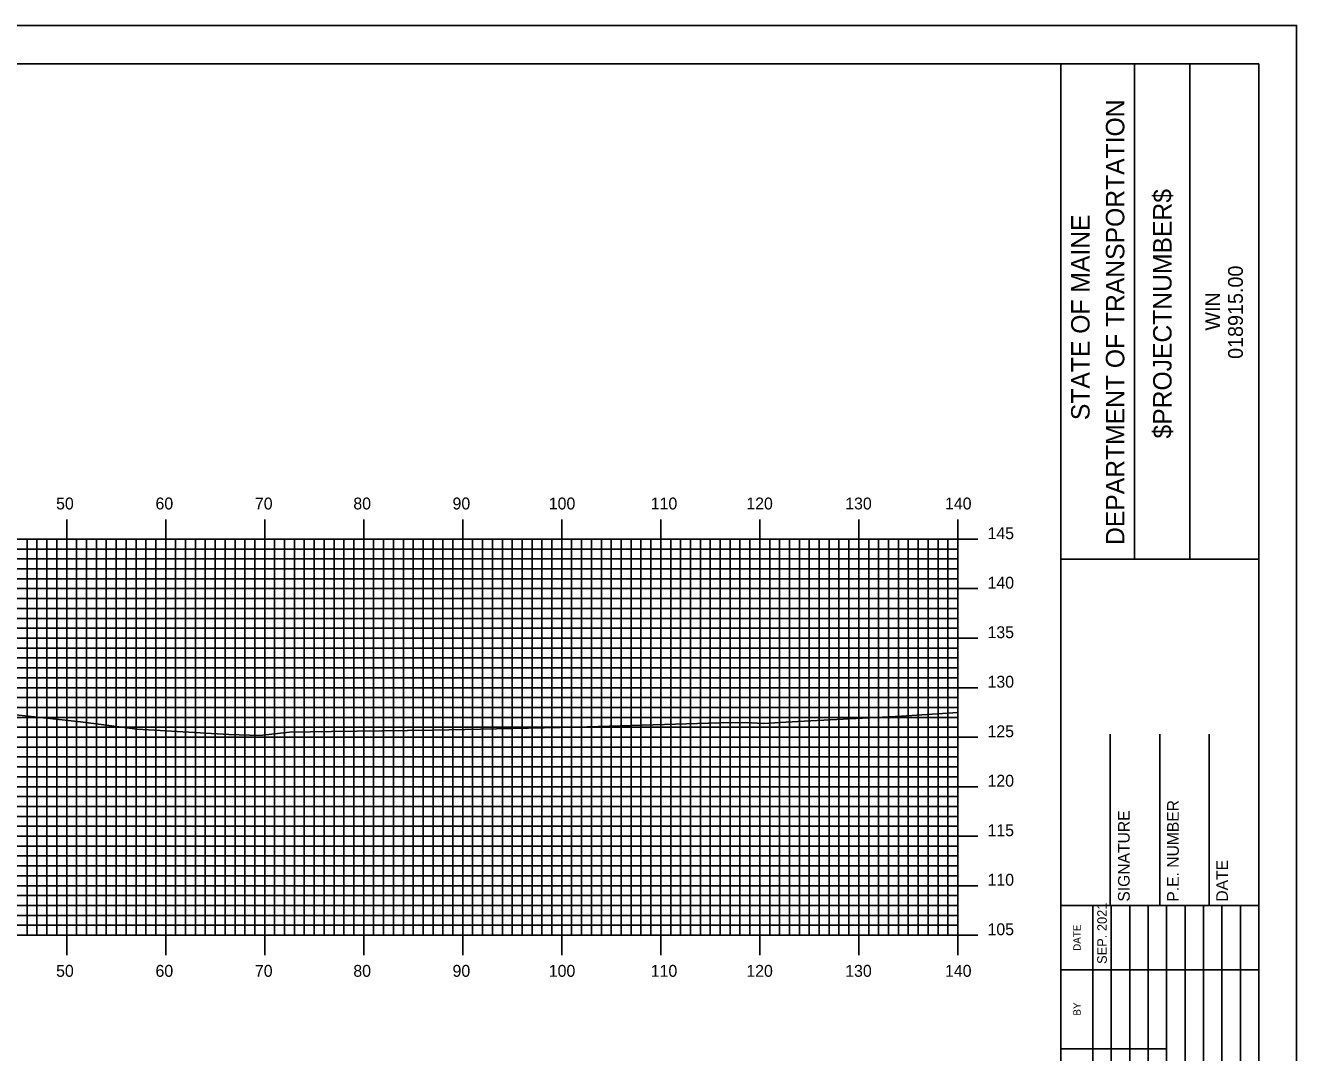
# Model space of a CAD drawing. Extents: x 851753 to 852097, y 364661 to 364881.
# Drawn here: x 851965.1 to 852093.5, y 364777.5 to 364881.3 of the extents above; entities that cross this region are included whole.
import ezdxf

# ---------------------------------------------------------------- set-up
doc = ezdxf.new("R2010")
doc.units = 0
for name, color, linetype in [('BORDER', 7, 'Continuous'), ('H_V ANNOTATION', 7, 'Continuous'), ('MAJOR', 7, 'Continuous'), ('MINOR', 7, 'Continuous'), ('PLOT BOUNDARY', 7, 'Continuous'), ('S_Roadway_Centerline', 7, 'Continuous')]:
    doc.layers.add(name, color=color, linetype=linetype)

msp = doc.modelspace()

# ---------------------------------------------------------------- linework, layer by layer
at = {"layer": 'BORDER'}
for p, q in [((852069.64, 364667.37), (852069.64, 364877.37)), ((852077.1, 364827.36), (852077.1, 364877.36)), ((852082.69, 364827.36), (852082.69, 364877.36)), ((852069.64, 364827.36), (852089.64, 364827.36)), ((852074.64, 364792.38), (852074.64, 364809.67)), ((852079.64, 364792.38), (852079.64, 364809.67)), ((852084.64, 364792.38), (852084.64, 364809.67)), ((852069.64, 364792.38), (852089.64, 364792.38))]:
    msp.add_line(p, q, dxfattribs=at)
msp.add_lwpolyline([(851769.64, 364667.37), (852089.64, 364667.37), (852089.64, 364877.37), (851769.64, 364877.37)], close=True, dxfattribs=at)
for points in [[(852072.87, 364785.88), (852072.87, 364792.38)], [(852074.74, 364757.38), (852074.74, 364792.38)], [(852076.6, 364792.38), (852076.6, 364757.38)], [(852078.46, 364757.38), (852078.46, 364792.38)], [(852080.33, 364757.38), (852080.33, 364792.38)], [(852082.19, 364757.38), (852082.19, 364792.38)], [(852084.05, 364757.38), (852084.05, 364792.38)], [(852085.92, 364757.38), (852085.92, 364792.38)], [(852087.78, 364757.38), (852087.78, 364792.38)], [(852072.87, 364757.38), (852072.87, 364790.96)], [(852069.64, 364785.88), (852089.64, 364785.88)], [(852069.64, 364777.88), (852072.87, 364777.88)], [(852072.87, 364777.88), (852080.33, 364777.88)]]:
    msp.add_lwpolyline(points, dxfattribs=at)
at = {"layer": 'MAJOR'}
for p, q in [((851969.24, 364831.37), (851969.24, 364829.37)), ((851979.24, 364831.37), (851979.24, 364829.37)), ((851989.24, 364831.37), (851989.24, 364829.37)), ((851999.24, 364831.37), (851999.24, 364829.37)), ((852009.24, 364831.37), (852009.24, 364829.37)), ((852019.24, 364831.37), (852019.24, 364829.37)), ((852029.24, 364831.37), (852029.24, 364829.37)), ((852039.24, 364831.37), (852039.24, 364829.37)), ((852049.24, 364831.37), (852049.24, 364829.37)), ((852059.24, 364831.37), (852059.24, 364829.37)), ((851779.24, 364829.37), (852059.24, 364829.37)), ((851779.24, 364829.37), (852059.24, 364829.37)), ((851969.24, 364789.37), (851969.24, 364829.37)), ((851979.24, 364789.37), (851979.24, 364829.37)), ((851989.24, 364789.37), (851989.24, 364829.37)), ((851999.24, 364789.37), (851999.24, 364829.37)), ((852009.24, 364789.37), (852009.24, 364829.37)), ((852019.24, 364789.37), (852019.24, 364829.37)), ((852029.24, 364789.37), (852029.24, 364829.37)), ((852039.24, 364789.37), (852039.24, 364829.37)), ((852049.24, 364789.37), (852049.24, 364829.37)), ((852061.25, 364829.37), (852057.24, 364829.37)), ((852059.24, 364789.37), (852059.24, 364829.37)), ((852059.24, 364789.37), (852059.24, 364829.37)), ((851779.24, 364824.37), (852059.24, 364824.37)), ((852061.25, 364824.37), (852057.24, 364824.37)), ((851779.24, 364819.37), (852059.24, 364819.37)), ((852061.25, 364819.37), (852057.24, 364819.37)), ((851779.24, 364814.37), (852059.24, 364814.37)), ((852061.25, 364814.37), (852057.24, 364814.37)), ((851779.24, 364809.37), (852059.24, 364809.37)), ((852061.25, 364809.37), (852057.24, 364809.37)), ((851779.24, 364804.37), (852059.24, 364804.37)), ((852061.25, 364804.37), (852057.24, 364804.37)), ((851779.24, 364799.37), (852059.24, 364799.37)), ((852061.25, 364799.37), (852057.24, 364799.37)), ((851779.24, 364794.37), (852059.24, 364794.37)), ((852061.25, 364794.37), (852057.24, 364794.37)), ((851779.24, 364789.37), (852059.24, 364789.37)), ((851779.24, 364789.37), (852059.24, 364789.37)), ((851969.24, 364787.37), (851969.24, 364789.37)), ((851979.24, 364787.37), (851979.24, 364789.37)), ((851989.24, 364787.37), (851989.24, 364789.37)), ((851999.24, 364787.37), (851999.24, 364789.37)), ((852009.24, 364787.37), (852009.24, 364789.37)), ((852019.24, 364787.37), (852019.24, 364789.37)), ((852029.24, 364787.37), (852029.24, 364789.37)), ((852039.24, 364787.37), (852039.24, 364789.37)), ((852049.24, 364787.37), (852049.24, 364789.37)), ((852061.25, 364789.37), (852057.24, 364789.37)), ((852059.24, 364787.37), (852059.24, 364789.37))]:
    msp.add_line(p, q, dxfattribs=at)
at = {"layer": 'MINOR'}
for p, q in [((851965.24, 364789.37), (851965.24, 364829.37)), ((851966.24, 364789.37), (851966.24, 364829.37)), ((851967.24, 364789.37), (851967.24, 364829.37)), ((851968.24, 364789.37), (851968.24, 364829.37)), ((851970.24, 364789.37), (851970.24, 364829.37)), ((851971.24, 364789.37), (851971.24, 364829.37)), ((851972.24, 364789.37), (851972.24, 364829.37)), ((851973.24, 364789.37), (851973.24, 364829.37)), ((851974.24, 364789.37), (851974.24, 364829.37)), ((851975.24, 364789.37), (851975.24, 364829.37)), ((851976.24, 364789.37), (851976.24, 364829.37)), ((851977.24, 364789.37), (851977.24, 364829.37)), ((851978.24, 364789.37), (851978.24, 364829.37)), ((851980.24, 364789.37), (851980.24, 364829.37)), ((851981.24, 364789.37), (851981.24, 364829.37)), ((851982.24, 364789.37), (851982.24, 364829.37)), ((851983.24, 364789.37), (851983.24, 364829.37)), ((851984.24, 364789.37), (851984.24, 364829.37)), ((851985.24, 364789.37), (851985.24, 364829.37)), ((851986.24, 364789.37), (851986.24, 364829.37)), ((851987.24, 364789.37), (851987.24, 364829.37)), ((851988.24, 364789.37), (851988.24, 364829.37)), ((851990.24, 364789.37), (851990.24, 364829.37)), ((851991.24, 364789.37), (851991.24, 364829.37)), ((851992.24, 364789.37), (851992.24, 364829.37)), ((851993.24, 364789.37), (851993.24, 364829.37)), ((851994.24, 364789.37), (851994.24, 364829.37)), ((851995.24, 364789.37), (851995.24, 364829.37)), ((851996.24, 364789.37), (851996.24, 364829.37)), ((851997.24, 364789.37), (851997.24, 364829.37)), ((851998.24, 364789.37), (851998.24, 364829.37)), ((852000.24, 364789.37), (852000.24, 364829.37)), ((852001.24, 364789.37), (852001.24, 364829.37)), ((852002.24, 364789.37), (852002.24, 364829.37)), ((852003.24, 364789.37), (852003.24, 364829.37)), ((852004.24, 364789.37), (852004.24, 364829.37)), ((852005.24, 364789.37), (852005.24, 364829.37)), ((852006.24, 364789.37), (852006.24, 364829.37)), ((852007.24, 364789.37), (852007.24, 364829.37)), ((852008.24, 364789.37), (852008.24, 364829.37)), ((852010.24, 364789.37), (852010.24, 364829.37)), ((852011.24, 364789.37), (852011.24, 364829.37)), ((852012.24, 364789.37), (852012.24, 364829.37)), ((852013.24, 364789.37), (852013.24, 364829.37)), ((852014.24, 364789.37), (852014.24, 364829.37)), ((852015.24, 364789.37), (852015.24, 364829.37)), ((852016.24, 364789.37), (852016.24, 364829.37)), ((852017.24, 364789.37), (852017.24, 364829.37)), ((852018.24, 364789.37), (852018.24, 364829.37)), ((852020.24, 364789.37), (852020.24, 364829.37)), ((852021.24, 364789.37), (852021.24, 364829.37)), ((852022.24, 364789.37), (852022.24, 364829.37)), ((852023.24, 364789.37), (852023.24, 364829.37)), ((852024.24, 364789.37), (852024.24, 364829.37)), ((852025.24, 364789.37), (852025.24, 364829.37)), ((852026.24, 364789.37), (852026.24, 364829.37)), ((852027.24, 364789.37), (852027.24, 364829.37)), ((852028.24, 364789.37), (852028.24, 364829.37)), ((852030.24, 364789.37), (852030.24, 364829.37)), ((852031.24, 364789.37), (852031.24, 364829.37)), ((852032.24, 364789.37), (852032.24, 364829.37)), ((852033.24, 364789.37), (852033.24, 364829.37)), ((852034.24, 364789.37), (852034.24, 364829.37)), ((852035.24, 364789.37), (852035.24, 364829.37)), ((852036.24, 364789.37), (852036.24, 364829.37)), ((852037.24, 364789.37), (852037.24, 364829.37)), ((852038.24, 364789.37), (852038.24, 364829.37)), ((852040.24, 364789.37), (852040.24, 364829.37)), ((852041.24, 364789.37), (852041.24, 364829.37)), ((852042.24, 364789.37), (852042.24, 364829.37)), ((852043.24, 364789.37), (852043.24, 364829.37)), ((852044.24, 364789.37), (852044.24, 364829.37)), ((852045.24, 364789.37), (852045.24, 364829.37)), ((852046.24, 364789.37), (852046.24, 364829.37)), ((852047.24, 364789.37), (852047.24, 364829.37)), ((852048.24, 364789.37), (852048.24, 364829.37)), ((852050.24, 364789.37), (852050.24, 364829.37)), ((852051.24, 364789.37), (852051.24, 364829.37)), ((852052.24, 364789.37), (852052.24, 364829.37)), ((852053.24, 364789.37), (852053.24, 364829.37)), ((852054.24, 364789.37), (852054.24, 364829.37)), ((852055.24, 364789.37), (852055.24, 364829.37)), ((852056.24, 364789.37), (852056.24, 364829.37)), ((852057.24, 364789.37), (852057.24, 364829.37)), ((852058.24, 364789.37), (852058.24, 364829.37)), ((851779.24, 364828.37), (852059.24, 364828.37)), ((852059.24, 364828.37), (852057.24, 364828.37)), ((851779.24, 364827.37), (852059.24, 364827.37)), ((852059.24, 364827.37), (852057.24, 364827.37)), ((851779.24, 364826.37), (852059.24, 364826.37)), ((851779.24, 364825.37), (852059.24, 364825.37)), ((852059.24, 364826.37), (852057.24, 364826.37)), ((852059.24, 364825.37), (852057.24, 364825.37)), ((851779.24, 364823.37), (852059.24, 364823.37)), ((852059.24, 364823.37), (852057.24, 364823.37)), ((851779.24, 364822.37), (852059.24, 364822.37)), ((852059.24, 364822.37), (852057.24, 364822.37)), ((851779.24, 364821.37), (852059.24, 364821.37)), ((851779.24, 364820.37), (852059.24, 364820.37)), ((852059.24, 364821.37), (852057.24, 364821.37)), ((852059.24, 364820.37), (852057.24, 364820.37)), ((851779.24, 364818.37), (852059.24, 364818.37)), ((852059.24, 364818.37), (852057.24, 364818.37)), ((851779.24, 364817.37), (852059.24, 364817.37)), ((851779.24, 364816.37), (852059.24, 364816.37)), ((852059.24, 364817.37), (852057.24, 364817.37)), ((852059.24, 364816.37), (852057.24, 364816.37)), ((851779.24, 364815.37), (852059.24, 364815.37)), ((852059.24, 364815.37), (852057.24, 364815.37)), ((851779.24, 364813.37), (852059.24, 364813.37)), ((852059.24, 364813.37), (852057.24, 364813.37)), ((851779.24, 364812.37), (852059.24, 364812.37)), ((851779.24, 364811.37), (852059.24, 364811.37)), ((852059.24, 364812.37), (852057.24, 364812.37)), ((852059.24, 364811.37), (852057.24, 364811.37)), ((851779.24, 364810.37), (852059.24, 364810.37)), ((852059.24, 364810.37), (852057.24, 364810.37)), ((851779.24, 364808.37), (852059.24, 364808.37)), ((851779.24, 364807.37), (852059.24, 364807.37)), ((852059.24, 364808.37), (852057.24, 364808.37)), ((852059.24, 364807.37), (852057.24, 364807.37)), ((851779.24, 364806.37), (852059.24, 364806.37)), ((852059.24, 364806.37), (852057.24, 364806.37)), ((851779.24, 364805.37), (852059.24, 364805.37)), ((852059.24, 364805.37), (852057.24, 364805.37)), ((851779.24, 364803.37), (852059.24, 364803.37)), ((851779.24, 364802.37), (852059.24, 364802.37)), ((852059.24, 364803.37), (852057.24, 364803.37)), ((852059.24, 364802.37), (852057.24, 364802.37)), ((851779.24, 364801.37), (852059.24, 364801.37)), ((852059.24, 364801.37), (852057.24, 364801.37)), ((851779.24, 364800.37), (852059.24, 364800.37)), ((852059.24, 364800.37), (852057.24, 364800.37)), ((851779.24, 364798.37), (852059.24, 364798.37)), ((852059.24, 364798.37), (852057.24, 364798.37)), ((851779.24, 364797.37), (852059.24, 364797.37)), ((852059.24, 364797.37), (852057.24, 364797.37)), ((851779.24, 364796.37), (852059.24, 364796.37)), ((852059.24, 364796.37), (852057.24, 364796.37)), ((851779.24, 364795.37), (852059.24, 364795.37)), ((852059.24, 364795.37), (852057.24, 364795.37)), ((851779.24, 364793.37), (852059.24, 364793.37)), ((852059.24, 364793.37), (852057.24, 364793.37)), ((851779.24, 364792.37), (852059.24, 364792.37)), ((852059.24, 364792.37), (852057.24, 364792.37)), ((851779.24, 364791.37), (852059.24, 364791.37)), ((852059.24, 364791.37), (852057.24, 364791.37)), ((851779.24, 364790.37), (852059.24, 364790.37)), ((852059.24, 364790.37), (852057.24, 364790.37))]:
    msp.add_line(p, q, dxfattribs=at)
at = {"layer": 'PLOT BOUNDARY'}
msp.add_lwpolyline([(851753.46, 364661.25), (852093.46, 364661.25), (852093.46, 364881.25), (851753.46, 364881.25)], close=True, dxfattribs=at)
at = {"layer": 'S_Roadway_Centerline'}
msp.add_lwpolyline([(851956.94, 364812.41), (851970.64, 364810.91), (851976.37, 364810.17), (851985.62, 364809.64), (851988.76, 364809.53), (851991.75, 364809.86), (851995.97, 364809.93), (852006.23, 364810.09), (852020.7, 364810.38), (852024.02, 364810.48), (852035.16, 364810.81), (852037.84, 364810.86), (852039.57, 364810.75), (852043.09, 364810.94), (852053.55, 364811.48), (852059.24, 364811.87)], dxfattribs=at)

# ---------------------------------------------------------------- texts
at = {"layer": 'BORDER'}
for s, height, p in [('DEPARTMENT OF TRANSPORTATION', 1.8635, (852076.06, 364828.78)), ('$PROJECTNUMBER$', 1.8635, (852080.83, 364839.53)), ('STATE OF MAINE', 1.8635, (852072.55, 364841.39)), ('018915.00', 1.491, (852088.03, 364847.57)), ('WIN', 1.491, (852085.72, 364850.43)), ('P.E. NUMBER', 1.1811, (852081.56, 364792.76)), ('SIGNATURE', 1.181, (852076.6, 364792.76)), ('DATE', 1.181, (852086.52, 364792.76)), ('SEP. 2021', 0.969, (852074.29, 364786.47)), ('DATE', 0.743, (852071.65, 364787.79)), ('BY', 0.743, (852071.65, 364781.25))]:
    msp.add_text(s, height=height, rotation=90, dxfattribs=at).set_placement(p)
at = {"layer": 'H_V ANNOTATION'}
for s, p in [('50', (851968.17, 364832.37)), ('60', (851978.21, 364832.37)), ('70', (851988.25, 364832.37)), ('80', (851998.19, 364832.37)), ('90', (852008.21, 364832.37)), ('100', (852017.93, 364832.37)), ('110', (852028.23, 364832.37)), ('120', (852037.88, 364832.37)), ('130', (852047.87, 364832.37)), ('140', (852057.95, 364832.37)), ('145', (852062.24, 364829.37)), ('140', (852062.24, 364824.37)), ('135', (852062.24, 364819.37)), ('130', (852062.24, 364814.37)), ('125', (852062.24, 364809.37)), ('120', (852062.24, 364804.37)), ('115', (852062.24, 364799.37)), ('110', (852062.24, 364794.37)), ('105', (852062.24, 364789.37)), ('50', (851968.17, 364785.17)), ('60', (851978.21, 364785.17)), ('70', (851988.25, 364785.17)), ('80', (851998.19, 364785.17)), ('90', (852008.21, 364785.17)), ('100', (852017.93, 364785.17)), ('110', (852028.23, 364785.17)), ('120', (852037.88, 364785.17)), ('130', (852047.87, 364785.17)), ('140', (852057.95, 364785.17))]:
    msp.add_text(s, height=1.2, dxfattribs=at).set_placement(p)

doc.saveas('drawing.dxf')
